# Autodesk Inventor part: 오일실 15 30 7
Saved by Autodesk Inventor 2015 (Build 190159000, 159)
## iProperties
Created: 2025-08
Part Number: 오일실 15 30 7
Material: 일반
Document SubType Name: Modeling
Designer: USER
Density: 1 g/cm^3
Appearance: 기본값
Author: USER
Author: jhkim
Description: 오일-실
Creation Date: 2025-08-05
Sending System: Autodesk Inventor 2026
Preprocessor: ST-DEVELOPER v20.1
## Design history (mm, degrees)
node "오일실 15 30 71"
body "Solid1"
node "기준1"
